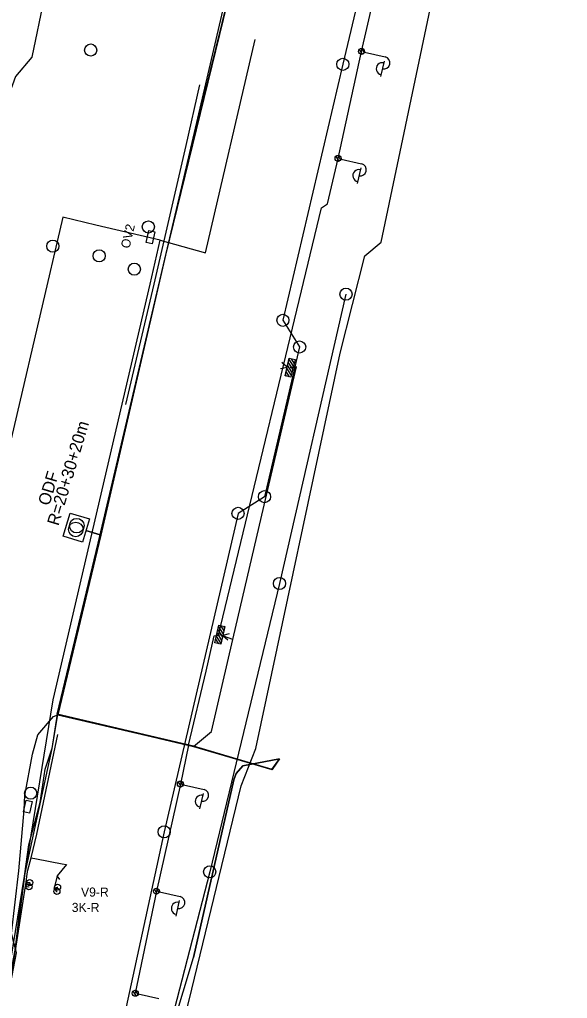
# Model space of a CAD drawing. Extents: x -748507 to -687366, y -1057342 to -1024924.
# Drawn here: x -743359.2 to -743268.9, y -1034916 to -1034754.6 of the extents above; entities that cross this region are included whole.
import ezdxf

# ---------------------------------------------------------------- set-up
doc = ezdxf.new("R2010")
doc.units = 0
for name, color, linetype in [('DK + TKK - SŽDC', 7, 'Continuous'), ('DK - Pha Holešovice - Kralupy - ČD TELEMATIKA', 7, 'Continuous'), ('kanalizace ČD', 7, 'Continuous'), ('Sděl MK - SŽDC', 7, 'Continuous'), ('Telefonica O2', 7, 'Continuous'), ('TK+DOK_Pha Holešovice - Kralupy', 7, 'Continuous'), ('Vedení NN - SŽDC', 7, 'Continuous')]:
    doc.layers.add(name, color=color, linetype=linetype)

msp = doc.modelspace()

# ---------------------------------------------------------------- linework, layer by layer
at = {"layer": 'DK + TKK - SŽDC'}
for p, q in [((-743357.6, -1034896.92), (-743357.5, -1034896.92)), ((-743357.72, -1034897.61), (-743357.62, -1034897.61)), ((-743353.12, -1034898.36), (-743353.02, -1034898.36)), ((-743353, -1034897.67), (-743352.9, -1034897.67))]:
    msp.add_line(p, q, dxfattribs=at)
for points in [[(-743352.85, -1034869.25), (-743345.75, -1034839.63), (-743335.08, -1034793.5), (-743334.25, -1034789.71), (-743332.49, -1034782.2), (-743315.44, -1034713.05)], [(-743352.85, -1034869.25), (-743330.54, -1034874.41), (-743317.58, -1034878.25), (-743316.35, -1034876.52)], [(-743357.32, -1034892.86), (-743356.39, -1034888.92), (-743352.94, -1034872.52)], [(-743316.35, -1034876.52), (-743322.4, -1034877.66), (-743323.52, -1034878.91), (-743323.9, -1034879.96), (-743330.53, -1034909.29)], [(-743359.88, -1034908.13), (-743358.27, -1034897.52), (-743358.16, -1034896.83), (-743357.95, -1034895.45), (-743357.87, -1034894.89), (-743357.32, -1034892.86)], [(-743357.32, -1034892.86), (-743356.42, -1034893.01), (-743352.19, -1034893.81), (-743351.49, -1034893.91), (-743353.01, -1034895.82), (-743353.51, -1034897.82)], [(-743352.57, -1034896.4), (-743353.01, -1034895.82)], [(-743358.27, -1034897.52), (-743357.67, -1034897.61)], [(-743358.16, -1034896.83), (-743357.55, -1034896.92)], [(-743353.07, -1034898.36), (-743353.51, -1034897.82), (-743352.95, -1034897.67)], [(-743338.6, -1034936.13), (-743332.26, -1034914.93), (-743330.53, -1034909.29)]]:
    msp.add_lwpolyline(points, dxfattribs=at)
for centre in [(-743357.67, -1034897.61), (-743357.55, -1034896.92), (-743352.95, -1034897.67), (-743353.07, -1034898.36)]:
    msp.add_circle(centre, 0.5, dxfattribs=at)
at = {"layer": 'DK - Pha Holešovice - Kralupy - ČD TELEMATIKA'}
for points in [[(-743377.03, -1035005.49), (-743368.34, -1034956.7), (-743353.7, -1034866.78), (-743337.71, -1034798.24), (-743336.02, -1034791), (-743346.65, -1034788.52), (-743352.11, -1034787.24), (-743371.09, -1034868.57), (-743398.01, -1034866.19), (-743383.8, -1034758.42)], [(-743336.02, -1034791), (-743328.55, -1034793.1), (-743320.35, -1034757.94)]]:
    msp.add_lwpolyline(points, dxfattribs=at)
at = {"layer": 'kanalizace ČD'}
for points in [[(-743320.22, -1034685.64), (-743311.98, -1034687.29), (-743313.16, -1034688.05), (-743316.05, -1034708.1), (-743309.01, -1034710.14), (-743304.5, -1034711.32), (-743294.49, -1034713.82), (-743305.93, -1034762.02), (-743315.8, -1034804.22), (-743313.05, -1034808.62), (-743318.85, -1034833.3), (-743323.2, -1034836.05), (-743335.39, -1034888.56), (-743346.79, -1034941.21), (-743354.46, -1034976.19), (-743364.11, -1034973.3), (-743371.04, -1034972.55), (-743376.7, -1034992.7)], [(-743341.69, -1034818.12), (-743337.05, -1034798.28), (-743331.73, -1034775.41), (-743329.48, -1034765.42)], [(-743305.4, -1034799.92), (-743316.37, -1034847.61), (-743327.87, -1034895.13), (-743340.38, -1034943.62)]]:
    msp.add_lwpolyline(points, dxfattribs=at)
for centre in [(-743347.5, -1034759.67), (-743305.93, -1034762.02), (-743353.73, -1034791.99), (-743346.09, -1034793.58), (-743340.3, -1034795.79), (-743305.4, -1034799.92), (-743315.8, -1034804.22), (-743313.05, -1034808.62), (-743318.85, -1034833.3), (-743323.2, -1034836.05), (-743316.37, -1034847.61), (-743335.39, -1034888.56), (-743327.87, -1034895.13)]:
    msp.add_circle(centre, 1, dxfattribs=at)
at = {"layer": 'Sděl MK - SŽDC'}
for p, q in [((-743314.29, -1034812.82), (-743315.04, -1034811.61)), ((-743314.17, -1034812.3), (-743314.92, -1034811.1)), ((-743314.05, -1034811.78), (-743314.8, -1034810.58)), ((-743313.93, -1034811.27), (-743314.38, -1034810.55)), ((-743313.81, -1034810.75), (-743313.86, -1034810.67)), ((-743315.23, -1034813.43), (-743315.4, -1034813.17)), ((-743314.72, -1034813.55), (-743315.28, -1034812.65)), ((-743314.41, -1034813.33), (-743315.16, -1034812.13)), ((-743326.54, -1034855.26), (-743325.79, -1034856.46)), ((-743326.42, -1034854.75), (-743325.67, -1034855.95)), ((-743326.11, -1034854.53), (-743325.55, -1034855.43)), ((-743325.6, -1034854.65), (-743325.43, -1034854.92)), ((-743326.9, -1034856.81), (-743326.45, -1034857.53)), ((-743326.78, -1034856.3), (-743326.03, -1034857.5)), ((-743326.66, -1034855.78), (-743325.91, -1034856.98)), ((-743327.02, -1034857.33), (-743326.97, -1034857.41))]:
    msp.add_line(p, q, dxfattribs=at)
for points in [[(-743352.91, -1034869.19), (-743345.75, -1034839.63), (-743335.08, -1034793.5), (-743334.25, -1034789.71), (-743332.49, -1034782.2), (-743325.48, -1034752.28), (-743315.44, -1034713.05), (-743314.23, -1034708.71), (-743302.64, -1034667.85), (-743295.54, -1034642.57), (-743291.41, -1034625.61), (-743289.65, -1034621.03), (-743288.28, -1034619.23), (-743271.7, -1034624.16), (-743271.33, -1034624.08), (-743270.8, -1034620.05), (-743268.89, -1034611.84)], [(-743352.85, -1034869.25), (-743345.75, -1034839.63), (-743335.08, -1034793.5), (-743334.25, -1034789.71), (-743332.49, -1034782.2), (-743315.44, -1034713.05)], [(-743324.06, -1034856.85), (-743318.53, -1034833.07), (-743313.56, -1034811.89), (-743314.62, -1034812.03)], [(-743316.2, -1034812.18), (-743315.11, -1034811.92), (-743315.97, -1034811.2)], [(-743315.45, -1034813.38), (-743314.77, -1034810.46), (-743313.79, -1034810.68), (-743314.47, -1034813.6), (-743315.45, -1034813.38)], [(-743325.38, -1034854.7), (-743326.06, -1034857.62), (-743327.04, -1034857.4), (-743326.36, -1034854.48), (-743325.38, -1034854.7)], [(-743330.54, -1034874.5), (-743327.58, -1034872.03), (-743324.06, -1034856.85), (-743326.21, -1034856.05)], [(-743324.64, -1034855.9), (-743325.72, -1034856.16), (-743324.86, -1034856.88)], [(-743361.61, -1034916.75), (-743359.94, -1034908.08), (-743358.94, -1034899.88), (-743357.7, -1034890.72), (-743355.82, -1034883.69), (-743355.02, -1034878.21), (-743353.87, -1034874.78), (-743352.91, -1034869.19), (-743330.54, -1034874.5), (-743317.61, -1034878.3), (-743316.35, -1034876.52)], [(-743389.13, -1035156.06), (-743387.37, -1035148.08), (-743387.18, -1035146.33), (-743386.88, -1035144.72), (-743387.12, -1035143.56), (-743386.93, -1035142.78), (-743386.76, -1035142.1), (-743379.13, -1035111.39), (-743375.75, -1035094.51), (-743374.01, -1035088.89), (-743372.49, -1035083.09), (-743367.9, -1035062.46), (-743363.88, -1035042.81), (-743355.68, -1035004.3), (-743352.88, -1034992.01), (-743349.48, -1034977.49), (-743347, -1034973.62), (-743346.31, -1034970.59), (-743345.39, -1034965.35), (-743345.49, -1034963.19), (-743338.6, -1034936.13), (-743332.26, -1034914.93), (-743330.53, -1034909.29), (-743323.9, -1034879.96)]]:
    msp.add_lwpolyline(points, dxfattribs=at)
for points in [[(-743315.45, -1034813.38), (-743314.77, -1034810.46), (-743313.79, -1034810.68), (-743314.47, -1034813.6)], [(-743325.38, -1034854.7), (-743326.06, -1034857.62), (-743327.04, -1034857.4), (-743326.36, -1034854.48)]]:
    msp.add_lwpolyline(points, close=True, dxfattribs=at)
at = {"layer": 'Telefonica O2'}
msp.add_lwpolyline([(-743355.16, -1034750.99), (-743357.18, -1034760.85), (-743359.92, -1034764.05), (-743360.87, -1034766.8), (-743365.52, -1034765.89)], dxfattribs=at)
at = {"layer": 'TK+DOK_Pha Holešovice - Kralupy'}
msp.add_line((-743351.01, -1034838.14), (-743350.98, -1034838.1), dxfattribs=at)
for points in [[(-743348.28, -1034838.87), (-743345.94, -1034839.57), (-743334.25, -1034789.71), (-743332.49, -1034782.2), (-743315.44, -1034713.05), (-743314.23, -1034708.71), (-743313.63, -1034706.6), (-743302.64, -1034667.85), (-743295.6, -1034642.52), (-743289.66, -1034619.88), (-743287.21, -1034611.85), (-743285.25, -1034610.91)], [(-743345.94, -1034839.57), (-743335.08, -1034793.5), (-743334.25, -1034789.71), (-743332.49, -1034782.2), (-743315.44, -1034713.05), (-743314.23, -1034708.71), (-743313.63, -1034706.6), (-743302.64, -1034667.85), (-743295.6, -1034642.52)], [(-743353.01, -1034869.17), (-743345.94, -1034839.57), (-743348.28, -1034838.87)], [(-743347, -1034973.62), (-743346.31, -1034970.59), (-743345.39, -1034965.35), (-743345.49, -1034963.19), (-743338.6, -1034936.13), (-743332.26, -1034914.93), (-743330.53, -1034909.29), (-743323.9, -1034879.96), (-743323.52, -1034878.91), (-743322.4, -1034877.66), (-743316.35, -1034876.52), (-743317.58, -1034878.25), (-743330.54, -1034874.41), (-743353.01, -1034869.17), (-743345.94, -1034839.57), (-743348.28, -1034838.87)], [(-743353.01, -1034869.17), (-743353.92, -1034874.82), (-743358.33, -1034895.34), (-743359.98, -1034908.21), (-743362.03, -1034922.73), (-743365.6, -1034955.73), (-743367.85, -1034965.91), (-743368.67, -1034969.72), (-743374.54, -1034999.58), (-743381.09, -1035030.83), (-743388.05, -1035062.38), (-743393.89, -1035088.93), (-743398.82, -1035111.05), (-743405.79, -1035141.35), (-743412.61, -1035171.74), (-743420.68, -1035207.17), (-743424.57, -1035211.33), (-743427.48, -1035221.1), (-743428.53, -1035225.12), (-743433.03, -1035244.31), (-743438.01, -1035261.61), (-743438.58, -1035265.06)], [(-743317.58, -1034878.25), (-743330.54, -1034874.41), (-743353.01, -1034869.17)], [(-743349.48, -1034977.49), (-743347, -1034973.62), (-743346.31, -1034970.59), (-743345.39, -1034965.35), (-743345.49, -1034963.19), (-743338.6, -1034936.13), (-743332.26, -1034914.93), (-743330.53, -1034909.29), (-743323.9, -1034879.96), (-743323.52, -1034878.91), (-743322.4, -1034877.66), (-743316.35, -1034876.52), (-743317.58, -1034878.25)]]:
    msp.add_lwpolyline(points, dxfattribs=at)
msp.add_lwpolyline([(-743352.03, -1034839.83), (-743350.9, -1034836.01), (-743347.71, -1034836.96), (-743348.85, -1034840.78)], close=True, dxfattribs=at)
for centre in [(-743349.95, -1034838.7), (-743349.79, -1034838.07)]:
    msp.add_circle(centre, 1.2, dxfattribs=at)
at = {"layer": 'Vedení NN - SŽDC'}
for p, q in [((-743303.21, -1034759.56), (-743302.71, -1034760.37)), ((-743302.87, -1034759.39), (-743302.41, -1034760.14)), ((-743302.35, -1034760), (-743298.95, -1034760.8)), ((-743299.1, -1034761.48), (-743299.7, -1034764.02)), ((-743307.08, -1034777.19), (-743306.58, -1034778)), ((-743306.74, -1034777.02), (-743306.28, -1034777.77)), ((-743306.22, -1034777.63), (-743302.82, -1034778.43)), ((-743302.97, -1034779.11), (-743303.57, -1034781.65)), ((-743333.08, -1034880.34), (-743332.57, -1034881.15)), ((-743332.75, -1034880.17), (-743332.28, -1034880.92)), ((-743332.22, -1034880.78), (-743328.81, -1034881.55)), ((-743328.96, -1034882.23), (-743329.54, -1034884.77)), ((-743337.02, -1034898), (-743336.51, -1034898.81)), ((-743336.69, -1034897.83), (-743336.22, -1034898.58)), ((-743336.16, -1034898.44), (-743332.75, -1034899.21)), ((-743332.9, -1034899.89), (-743333.48, -1034902.43)), ((-743340.53, -1034914.83), (-743340.01, -1034915.64)), ((-743340.19, -1034914.66), (-743339.72, -1034915.4)), ((-743339.66, -1034915.27), (-743336.24, -1034916.01))]:
    msp.add_line(p, q, dxfattribs=at)
for points in [[(-743352.92, -1034869.25), (-743345.75, -1034839.63), (-743335.08, -1034793.5), (-743315.44, -1034713.05), (-743305.35, -1034675.45), (-743295.56, -1034642.57), (-743295.29, -1034641.55), (-743291.69, -1034628.1), (-743286.74, -1034609.65), (-743286.05, -1034607.39)], [(-743343.96, -1034960.72), (-743342.1, -1034960.98), (-743338.7, -1034946.96), (-743338.03, -1034943.87), (-743330.82, -1034914.46), (-743322.71, -1034880.96), (-743320.24, -1034874.81), (-743306.37, -1034809.66), (-743302.28, -1034793.57), (-743299.61, -1034791.32), (-743283.23, -1034713.42), (-743280.02, -1034699.03), (-743280.72, -1034698.71)], [(-743413.03, -1035172.29), (-743402.89, -1035127.87), (-743393.84, -1035087.43), (-743386.11, -1035053.28), (-743381.72, -1035033.62), (-743376.3, -1035007.33), (-743371.61, -1034985.85), (-743373.14, -1034982.41), (-743368.87, -1034972.33), (-743367.76, -1034965.58), (-743365.78, -1034955.64), (-743364.53, -1034942.66), (-743362.23, -1034921.42), (-743359.73, -1034908.49), (-743360.53, -1034905.29), (-743359.37, -1034894.97), (-743358.47, -1034884.91), (-743358.38, -1034882.55), (-743357.07, -1034875.75), (-743356.19, -1034872.57), (-743353.64, -1034869.52), (-743352.92, -1034869.25), (-743335.08, -1034793.5), (-743315.44, -1034713.05)], [(-743331.38, -1034874.24), (-743328.48, -1034862.09), (-743327.15, -1034856.26), (-743326.42, -1034856.15), (-743309.43, -1034785.67), (-743308.43, -1034785), (-743306.71, -1034777.52), (-743302.84, -1034759.89), (-743298.99, -1034743.24)], [(-743337.37, -1034791.6), (-743338.34, -1034791.37), (-743337.89, -1034789.42), (-743336.92, -1034789.65), (-743337.37, -1034791.6)], [(-743357.07, -1034875.75), (-743356.19, -1034872.57), (-743353.64, -1034869.52), (-743352.92, -1034869.25), (-743331.38, -1034874.24), (-743332.71, -1034880.67), (-743336.65, -1034898.33), (-743340.15, -1034915.16)], [(-743368.87, -1034972.33), (-743367.76, -1034965.58), (-743365.78, -1034955.64), (-743364.53, -1034942.66), (-743362.23, -1034921.42), (-743359.73, -1034908.49), (-743360.53, -1034905.29), (-743359.37, -1034894.97), (-743358.47, -1034884.91), (-743358.38, -1034882.55), (-743357.07, -1034875.75)], [(-743357.59, -1034885.5), (-743358.57, -1034885.27), (-743358.11, -1034883.32), (-743357.14, -1034883.55), (-743357.59, -1034885.5)]]:
    msp.add_lwpolyline(points, dxfattribs=at)
for centre, radius in [((-743302.84, -1034759.89), 0.5), ((-743302.84, -1034759.89), 0.5), ((-743306.71, -1034777.52), 0.5), ((-743306.71, -1034777.52), 0.5), ((-743337.99, -1034788.83), 1), ((-743357.39, -1034882.18), 1), ((-743332.71, -1034880.67), 0.5), ((-743332.71, -1034880.67), 0.5), ((-743336.65, -1034898.33), 0.5), ((-743336.65, -1034898.33), 0.5), ((-743340.15, -1034915.16), 0.5), ((-743340.15, -1034915.16), 0.5)]:
    msp.add_circle(centre, radius, dxfattribs=at)
for centre, start, end in [((-743299.41, -1034762.75), 76.1263, 257.5314), ((-743299.17, -1034761.78), 256.8288, 76.8288), ((-743303.28, -1034780.38), 76.1263, 257.5314), ((-743303.04, -1034779.41), 256.8288, 76.8288), ((-743329.26, -1034883.5), 76.5662, 257.9714), ((-743329.03, -1034882.53), 257.2688, 77.2688), ((-743333.2, -1034901.16), 76.5662, 257.9714), ((-743332.97, -1034900.19), 257.2688, 77.2688)]:
    msp.add_arc(centre, 1, start, end, dxfattribs=at)

# ---------------------------------------------------------------- texts
at = {"layer": 'DK + TKK - SŽDC'}
for s, p in [('V9-R', (-743349.09, -1034899.23)), ('3K-R', (-743350.62, -1034901.76))]:
    msp.add_text(s, height=1.5, dxfattribs=at).set_placement(p)
at = {"layer": 'TK+DOK_Pha Holešovice - Kralupy'}
for s, p in [('R=20+30+20m', (-743352.81, -1034838.2)), ('ODF', (-743354.32, -1034834.9))]:
    msp.add_text(s, height=2, rotation=73.4131, dxfattribs=at).set_placement(p)
at = {"layer": 'Vedení NN - SŽDC'}
msp.add_text('OV2', height=1.5, rotation=76.8409, dxfattribs=at).set_placement((-743341.1, -1034792.47))

doc.saveas('drawing.dxf')
